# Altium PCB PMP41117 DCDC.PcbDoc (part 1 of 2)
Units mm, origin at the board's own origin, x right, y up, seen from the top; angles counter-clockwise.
Board outline 26.81 x 27.2 mm, 4 copper layers (Top Layer, Signal Layer 1, Signal Layer 2, Bottom Layer), stack 1.016 mm thick; 79 components, 59 nets, 285 pads, 212 vias.
Unrouted connection lines stored in the file: 2.
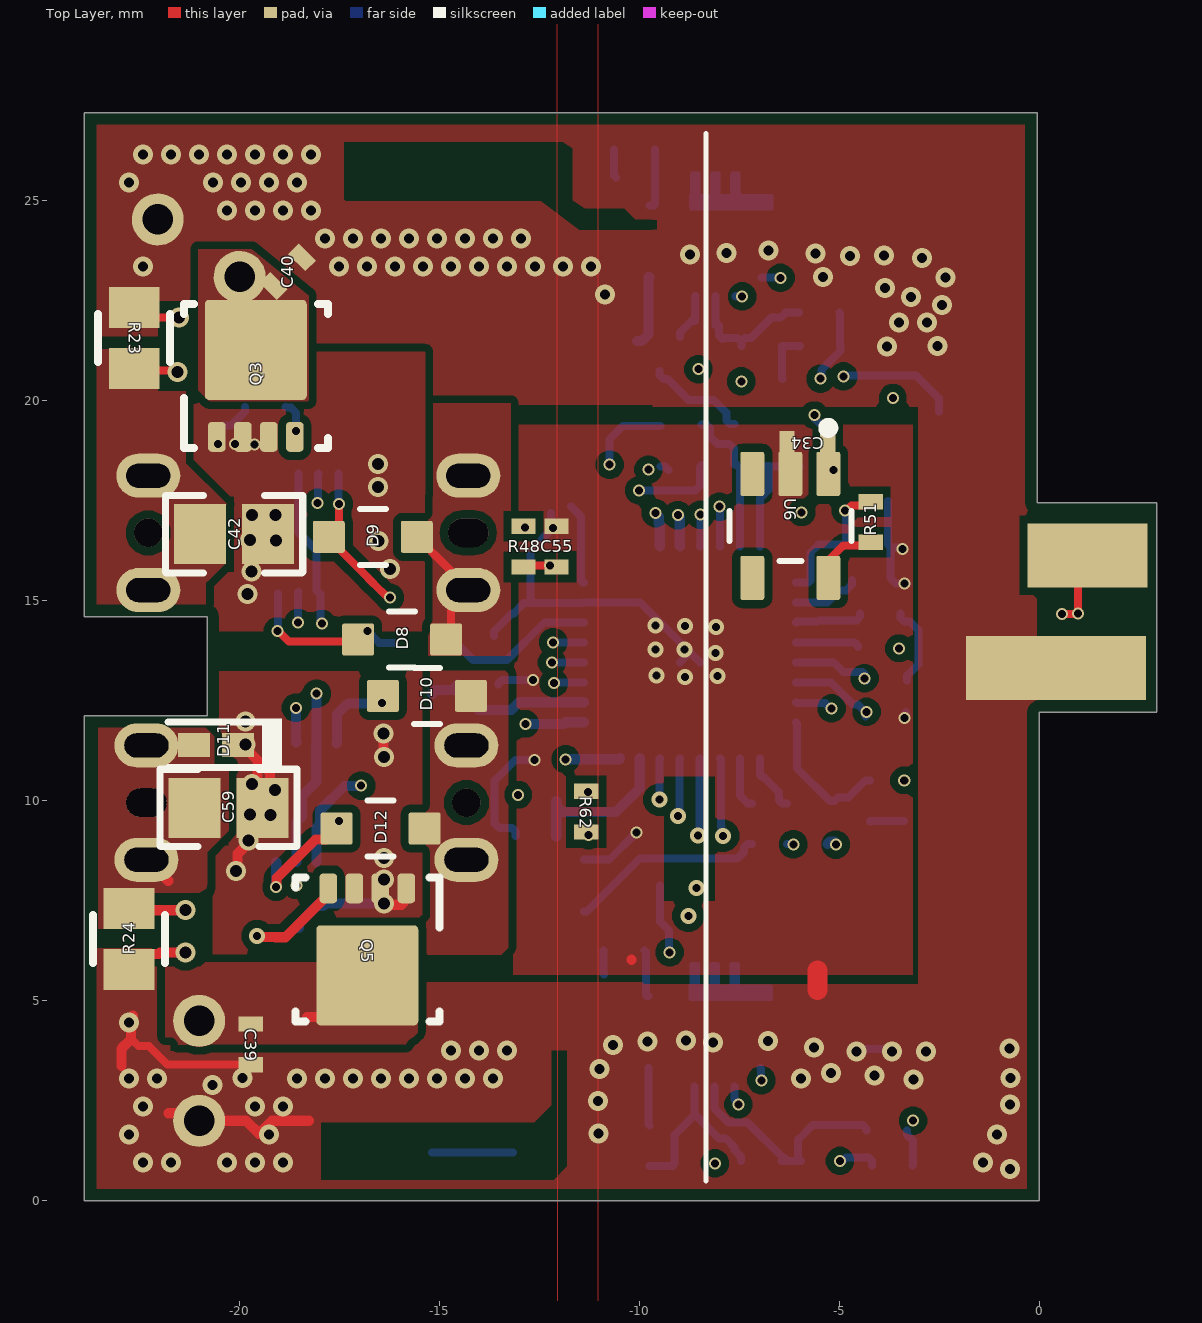
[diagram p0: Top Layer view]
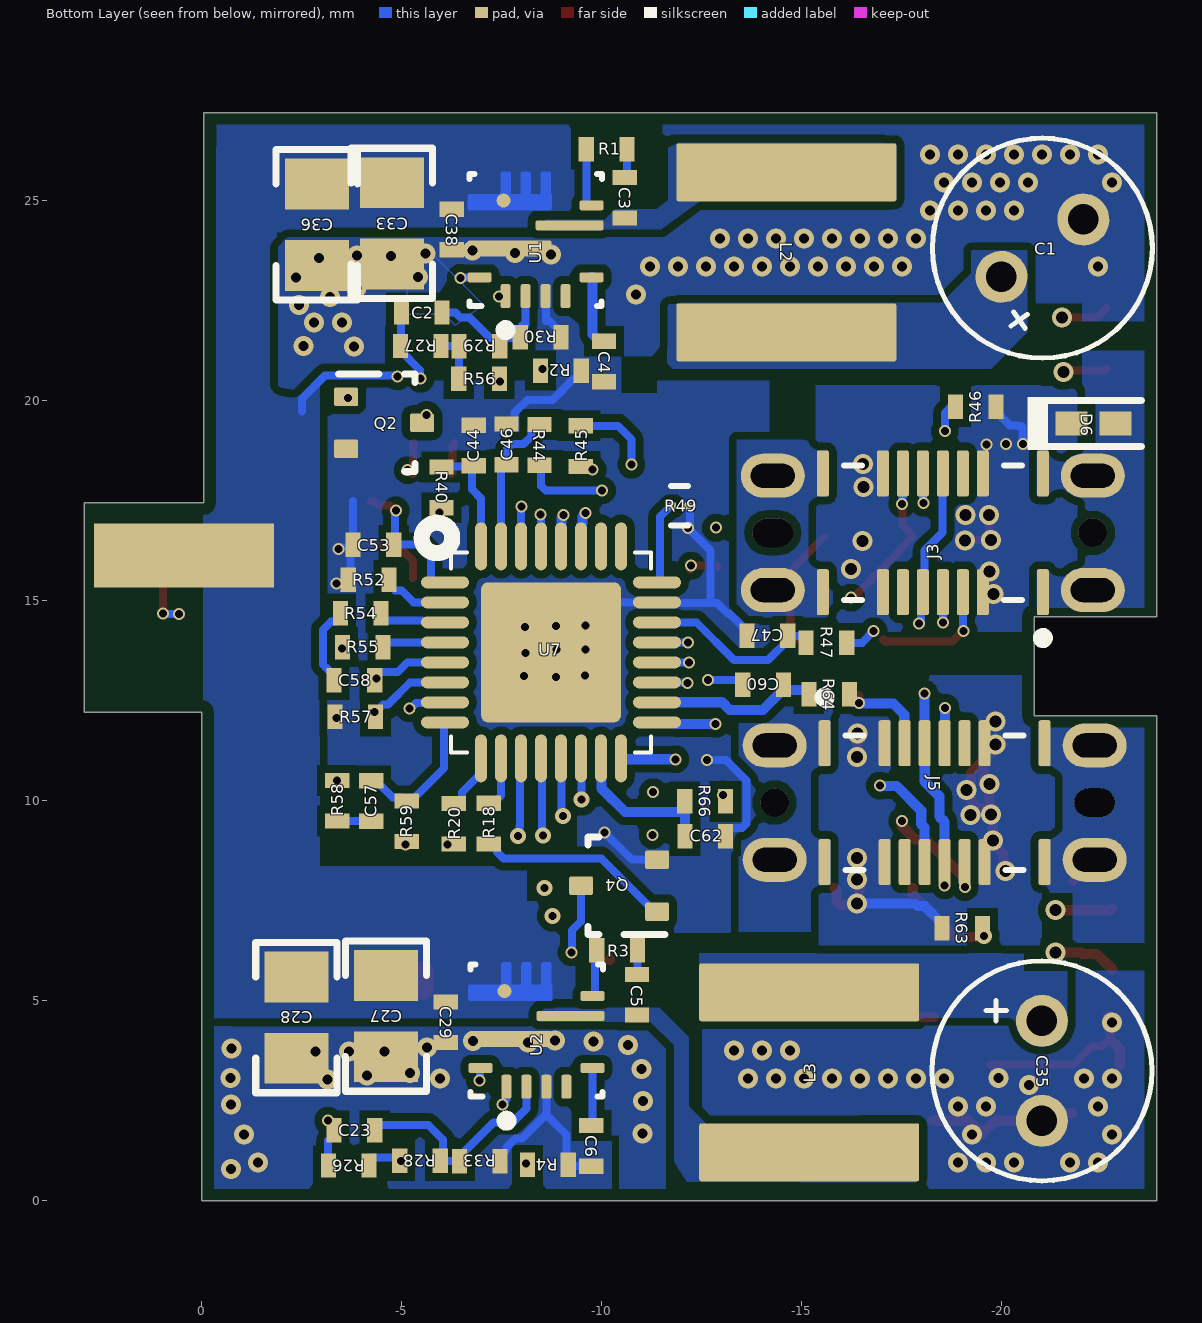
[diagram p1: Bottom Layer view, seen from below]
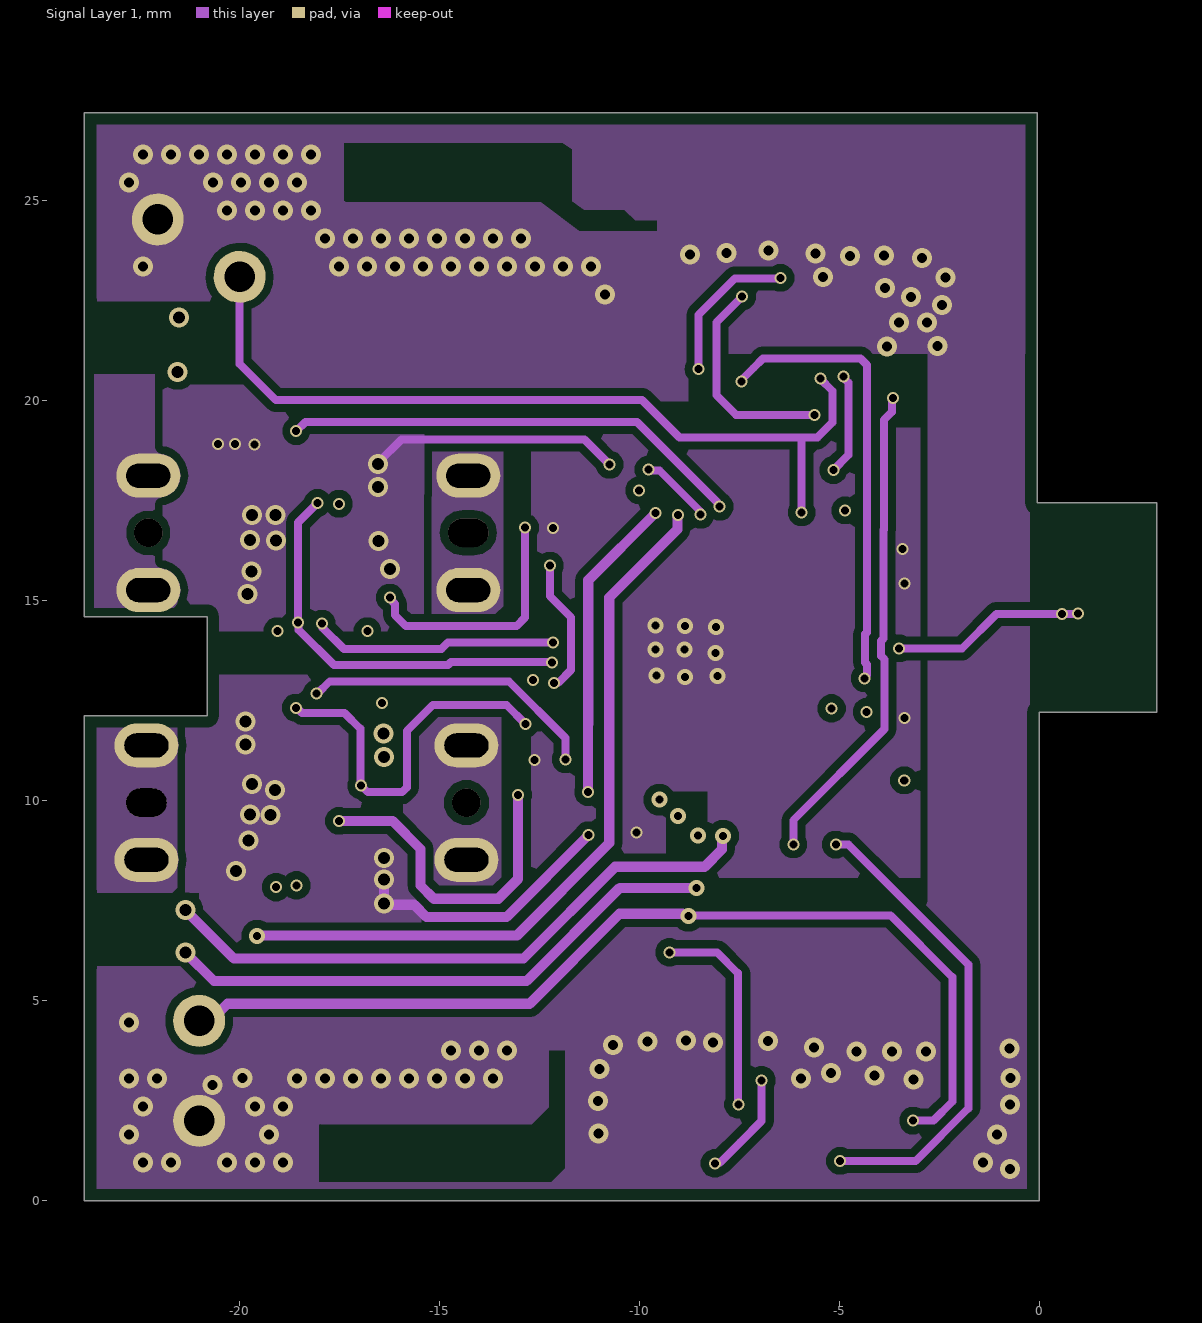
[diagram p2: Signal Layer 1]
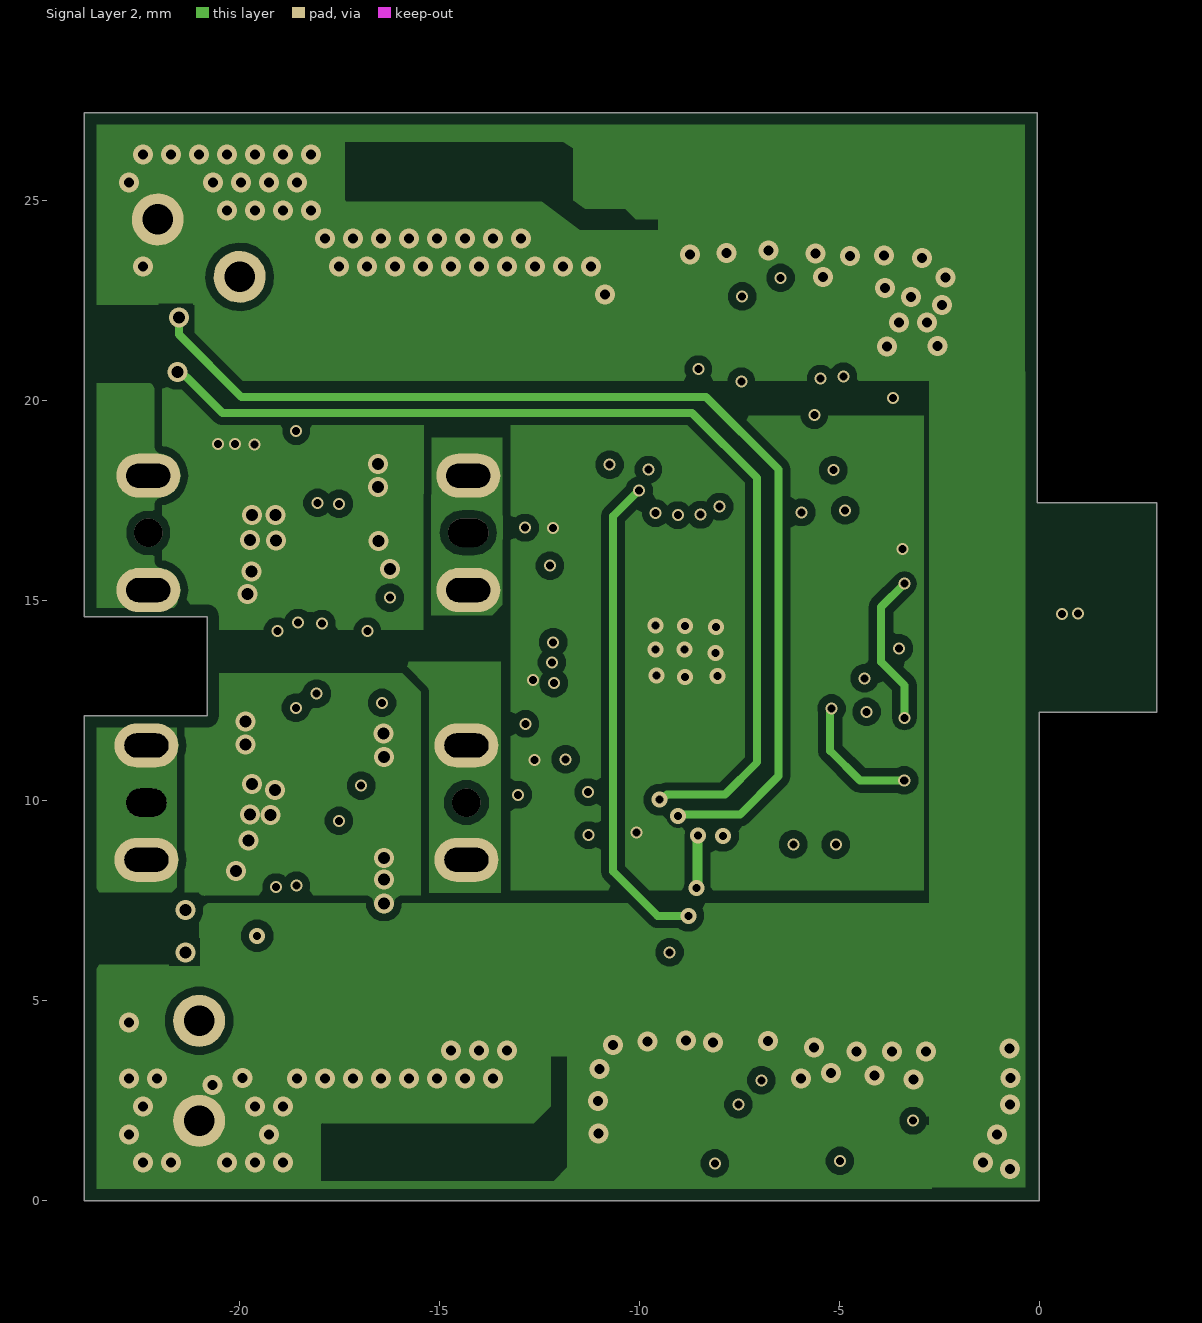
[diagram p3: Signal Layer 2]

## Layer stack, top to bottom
Top Solder: solder mask 0.0102, Solder Resist, Dk 3.5
Top Layer: signal copper 0.0711
Dielectric 1: prepreg 0.127, FR-4 High Tg, Dk 4.2
Signal Layer 1: signal copper 0.0356
Dielectric 2: core 0.5486, FR-4 High Tg, Dk 4.2
Signal Layer 2: signal copper 0.0356
Dielectric 3: prepreg 0.127, FR-4 High Tg, Dk 4.2
Bottom Layer: signal copper 0.0711
Bottom Solder: solder mask 0.0102, Solder Resist, Dk 3.5

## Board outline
-23.866,-0.008 -23.866,12.127 -20.803,12.127 -20.803,14.601 -23.87,14.601 -23.87,27.192 -23.866,27.196 -0.051,27.196 -0.051,17.446 2.94,17.446 2.94,12.211 0.002,12.211 0.002,-0.008

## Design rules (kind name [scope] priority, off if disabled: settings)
AcuteAngle [All] p1: minimum=4.50000000000000E+0001 checktracksonly=FALSE
AssemblyTestPointUsage [All] p1: valid=2
BoardOutlineClearance BoardOutlineClearance_MountingHoles [OnCopper and InComponentClass('Mounting Holes')] p1: gap=0.3 ignorepadtopadclearanceinfootprint=FALSE
BoardOutlineClearance BoardOutlineClearance_Poly [OnCopper and IsPoly] p2: gap=0.3 ignorepadtopadclearanceinfootprint=FALSE
BoardOutlineClearance [OnCopper and Not InComponentClass('Logo') and not InComponentClass('FiducialMark') and not InRegion(1000,500,4000,800) and not InPoly] p3: gap=0.3 ignorepadtopadclearanceinfootprint=FALSE
Clearance Clearance_VAC_PGND [InNetClass('VAC') vs InNetClass('PGND')] p1: gap=2.286 ignorepadtopadclearanceinfootprint=TRUE
Clearance Clearance_HV_PGND [InNetClass('High Voltage') vs InNetClass('PGND')] p2: gap=1.016 ignorepadtopadclearanceinfootprint=TRUE
Clearance Clearance_SW_PGND [InNetClass('Switch Node') vs InNetClass('PGND')] p3: gap=0.864 ignorepadtopadclearanceinfootprint=TRUE
Clearance Clearance_AC_AC [InNetClass('VAC') vs InNetClass('VAC')] p4: gap=1.524 ignorepadtopadclearanceinfootprint=TRUE
Clearance Clearance_PGND_SGND [InNetClass('PGND') vs InNetClass('SGND')] p5: gap=4.064 ignorepadtopadclearanceinfootprint=TRUE
Clearance Clearance_HV_LV [InNetClass('High Voltage') vs InNetClass('Low Voltage')] p6: gap=0.864 ignorepadtopadclearanceinfootprint=TRUE
Clearance Clearance_SW_LV_1 [InNetClass('Switch Node') vs InNetClass('Low Voltage')] p7: gap=0.864 ignorepadtopadclearanceinfootprint=TRUE
Clearance Clearance_SW_HV [InNetClass('Switch Node') vs InNetClass('High Voltage')] p8: gap=0.864 ignorepadtopadclearanceinfootprint=TRUE
Clearance Clearance_1 [All] p9: gap=0.2 ignorepadtopadclearanceinfootprint=TRUE
Clearance Clearance_Keepouts [((IsTrack Or IsArc) And Not InPoly) And IsFree and IsKeepOut vs ((IsTrack Or IsArc) And Not InPoly) And IsFree and IsKeepOut] p10: gap=0 ignorepadtopadclearanceinfootprint=FALSE
Clearance Clearance_Poly [InPolygon] p11: gap=0.254 ignorepadtopadclearanceinfootprint=TRUE
Clearance Clearance_FiducialMark [IsKeepOut and InComponentClass('FiducialMark') vs IsPad and InComponentClass('FiducialMark')] p12: gap=0 ignorepadtopadclearanceinfootprint=FALSE
ComponentClearance ComponentClearance_MountingHoles_FiducialMarks [InComponentClass('Mounting Holes') vs InComponentClass('FiducialMark')] p1: gap=0.2 collisioncheckmode=3 verticalgap=0.2 showdistances=FALSE
ComponentClearance ComponentClearance_Shunt [InComponentClass('Header') vs InComponentClass('Shunt')] p2: gap=0 collisioncheckmode=3 verticalgap=0 showdistances=FALSE
ComponentClearance ComponentClearance_Logo [InComponentClass('Logo')] p3: gap=0.2 collisioncheckmode=3 verticalgap=0.2 showdistances=FALSE
ComponentClearance ComponentClearance_ScrewToNut [(HasFootprint('NY PMS 440 0025 PH')) vs (HasFootprint('Keystone_1902C'))] p4: gap=0.127 collisioncheckmode=3 verticalgap=0.254 showdistances=FALSE
ComponentClearance ComponentClearance_MountingHoles [InComponentClass('Mounting Holes')] p5: gap=1 collisioncheckmode=3 verticalgap=2540 showdistances=FALSE
ComponentClearance ComponentClearance_SmallPassives [HasFootprint('0201*') or HasFootprint('0402*') or HasFootprint('0508') or HasFootprint('0603*') or HasFootprint('0612') or HasFootprint('0805*') or HasFootprint('0815*') or HasFootprint('0830*') or HasFootprint('1206*') or HasFootprint('1210*') or HasFootprint('1808*') or HasFootprint('1812*') or HasFootprint('1825*') or HasFootprint('2010*') or HasFootprint('2220*') or HasFootprint('2225*') or HasFootprint('2512*') or HasFootprint('2728*') or HasFootprint('3518*') vs HasFootprint('0201*') or HasFootprint('0402*') or HasFootprint('0508') or HasFootprint('0603*') or HasFootprint('0612') or HasFootprint('0805*') or HasFootprint('0815*') or HasFootprint('0830*') or HasFootprint('1206*') or HasFootprint('1210*') or HasFootprint('1808*') or HasFootprint('1812*') or HasFootprint('1825*') or HasFootprint('2010*') or HasFootprint('2220*') or HasFootprint('2225*') or HasFootprint('2512*') or HasFootprint('2728*') or HasFootprint('3518*')] p6: gap=0.2 collisioncheckmode=3 verticalgap=0.2 showdistances=FALSE
ComponentClearance ComponentClearance_THtoSMT [IsThruComponent vs IsSMTComponent] p7: gap=0.2 collisioncheckmode=3 verticalgap=0.2 showdistances=FALSE
ComponentClearance ComponentClearance_THtoTH [IsThruComponent vs IsThruComponent] p8: gap=0.2 collisioncheckmode=3 verticalgap=0.2 showdistances=FALSE
ComponentClearance [All] p9: gap=0.1 collisioncheckmode=3 verticalgap=0.1 showdistances=FALSE
DiffPairsRouting DiffPair_DiffPairsRouting [All] p1: maxlimit=0.254 minlimit=0.254 mostfreqgap=0.254 toplayer_minwidth=0.254 toplayer_maxwidth=0.254 toplayer_prefwidth=0.254 midlayer1_minwidth=0.254 midlayer1_maxwidth=0.254 midlayer1_prefwidth=0.254 midlayer2_minwidth=0.254 midlayer2_maxwidth=0.254 midlayer2_prefwidth=0.254 bottomlayer_minwidth=0.254 bottomlayer_maxwidth=0.254 bottomlayer_prefwidth=0.254 filterlayerstackid={9F2BDCAB-BF4A-4FAE-9F57-695CEC5DA6CF} maxuncoupledlength=12.7
DiffPairsRouting DiffPair_DiffPairsRouting_1 [InDifferentialPair ('NewDifferentialPair1')] p2: maxlimit=0.203 minlimit=0.203 mostfreqgap=0.203 toplayer_minwidth=0.254 toplayer_maxwidth=0.254 toplayer_prefwidth=0.254 midlayer1_minwidth=0.254 midlayer1_maxwidth=0.254 midlayer1_prefwidth=0.254 midlayer2_minwidth=0.254 midlayer2_maxwidth=0.254 midlayer2_prefwidth=0.254 bottomlayer_minwidth=0.254 bottomlayer_maxwidth=0.254 bottomlayer_prefwidth=0.254 filterlayerstackid={9F2BDCAB-BF4A-4FAE-9F57-695CEC5DA6CF} maxuncoupledlength=12.7
DiffPairsRouting DiffPair_DiffPairsRouting_2 [InDifferentialPair ('NewDifferentialPair1')] p3: maxlimit=0.127 minlimit=0.127 mostfreqgap=0.127 toplayer_minwidth=0.254 toplayer_maxwidth=0.254 toplayer_prefwidth=0.254 midlayer1_minwidth=0.254 midlayer1_maxwidth=0.254 midlayer1_prefwidth=0.254 midlayer2_minwidth=0.254 midlayer2_maxwidth=0.254 midlayer2_prefwidth=0.254 bottomlayer_minwidth=0.254 bottomlayer_maxwidth=0.254 bottomlayer_prefwidth=0.254 filterlayerstackid={9F2BDCAB-BF4A-4FAE-9F57-695CEC5DA6CF} maxuncoupledlength=12.7
DiffPairsRouting DiffPair_DiffPairsRouting_3 [InDifferentialPair ('NewDifferentialPair1')] p4: maxlimit=0.178 minlimit=0.178 mostfreqgap=0.178 toplayer_minwidth=0.254 toplayer_maxwidth=0.254 toplayer_prefwidth=0.254 midlayer1_minwidth=0.254 midlayer1_maxwidth=0.254 midlayer1_prefwidth=0.254 midlayer2_minwidth=0.254 midlayer2_maxwidth=0.254 midlayer2_prefwidth=0.254 bottomlayer_minwidth=0.254 bottomlayer_maxwidth=0.254 bottomlayer_prefwidth=0.254 filterlayerstackid={9F2BDCAB-BF4A-4FAE-9F57-695CEC5DA6CF} maxuncoupledlength=12.7
DiffPairsRouting DiffPair_DiffPairsRouting_4 [InDifferentialPair ('NewDifferentialPair1')] p5: maxlimit=0.254 minlimit=0.254 mostfreqgap=0.254 toplayer_minwidth=0.381 toplayer_maxwidth=0.381 toplayer_prefwidth=0.381 midlayer1_minwidth=0.381 midlayer1_maxwidth=0.381 midlayer1_prefwidth=0.381 midlayer2_minwidth=0.381 midlayer2_maxwidth=0.381 midlayer2_prefwidth=0.381 bottomlayer_minwidth=0.381 bottomlayer_maxwidth=0.381 bottomlayer_prefwidth=0.381 filterlayerstackid={9F2BDCAB-BF4A-4FAE-9F57-695CEC5DA6CF} maxuncoupledlength=12.7
DiffPairsRouting DiffPair_DiffPairsRouting_5 [All] p6: maxlimit=0.254 minlimit=0.254 mostfreqgap=0.254 toplayer_minwidth=0.254 toplayer_maxwidth=0.254 toplayer_prefwidth=0.254 midlayer1_minwidth=0.254 midlayer1_maxwidth=0.254 midlayer1_prefwidth=0.254 midlayer2_minwidth=0.254 midlayer2_maxwidth=0.254 midlayer2_prefwidth=0.254 bottomlayer_minwidth=0.254 bottomlayer_maxwidth=0.254 bottomlayer_prefwidth=0.254 filterlayerstackid={9F2BDCAB-BF4A-4FAE-9F57-695CEC5DA6CF} maxuncoupledlength=12.7
DiffPairsRouting DiffPair_DiffPairsRouting_6 [All] p7: maxlimit=0.254 minlimit=0.254 mostfreqgap=0.254 toplayer_minwidth=0.254 toplayer_maxwidth=0.254 toplayer_prefwidth=0.254 midlayer1_minwidth=0.254 midlayer1_maxwidth=0.254 midlayer1_prefwidth=0.254 midlayer2_minwidth=0.254 midlayer2_maxwidth=0.254 midlayer2_prefwidth=0.254 bottomlayer_minwidth=0.254 bottomlayer_maxwidth=0.254 bottomlayer_prefwidth=0.254 filterlayerstackid={9F2BDCAB-BF4A-4FAE-9F57-695CEC5DA6CF} maxuncoupledlength=12.7
DiffPairsRouting DiffPair_DiffPairsRouting_7 [InDifferentialPair ('NewDifferentialPair2')] p8: maxlimit=0.254 minlimit=0.254 mostfreqgap=0.254 toplayer_minwidth=0.254 toplayer_maxwidth=0.254 toplayer_prefwidth=0.254 midlayer1_minwidth=0.254 midlayer1_maxwidth=0.254 midlayer1_prefwidth=0.254 midlayer2_minwidth=0.254 midlayer2_maxwidth=0.254 midlayer2_prefwidth=0.254 bottomlayer_minwidth=0.254 bottomlayer_maxwidth=0.254 bottomlayer_prefwidth=0.254 filterlayerstackid={9F2BDCAB-BF4A-4FAE-9F57-695CEC5DA6CF} maxuncoupledlength=12.7
DiffPairsRouting DiffPair_DiffPairsRouting_8 [InDifferentialPair ('NewDifferentialPair2')] p9: maxlimit=0.254 minlimit=0.254 mostfreqgap=0.254 toplayer_minwidth=0.381 toplayer_maxwidth=0.381 toplayer_prefwidth=0.381 midlayer1_minwidth=0.381 midlayer1_maxwidth=0.381 midlayer1_prefwidth=0.381 midlayer2_minwidth=0.381 midlayer2_maxwidth=0.381 midlayer2_prefwidth=0.381 bottomlayer_minwidth=0.381 bottomlayer_maxwidth=0.381 bottomlayer_prefwidth=0.381 filterlayerstackid={9F2BDCAB-BF4A-4FAE-9F57-695CEC5DA6CF} maxuncoupledlength=12.7
DiffPairsRouting DiffPair_DiffPairsRouting_9 [InDifferentialPair ('ISense_A')] p10: maxlimit=0.198 minlimit=0.198 mostfreqgap=0.198 toplayer_minwidth=0.254 toplayer_maxwidth=0.254 toplayer_prefwidth=0.254 midlayer1_minwidth=0.254 midlayer1_maxwidth=0.254 midlayer1_prefwidth=0.254 midlayer2_minwidth=0.254 midlayer2_maxwidth=0.254 midlayer2_prefwidth=0.254 bottomlayer_minwidth=0.254 bottomlayer_maxwidth=0.254 bottomlayer_prefwidth=0.254 filterlayerstackid={9F2BDCAB-BF4A-4FAE-9F57-695CEC5DA6CF} maxuncoupledlength=12.7
DiffPairsRouting DiffPair_DiffPairsRouting_10 [InDifferentialPair ('ISense_A')] p11: maxlimit=0.254 minlimit=0.254 mostfreqgap=0.254 toplayer_minwidth=0.381 toplayer_maxwidth=0.381 toplayer_prefwidth=0.381 midlayer1_minwidth=0.381 midlayer1_maxwidth=0.381 midlayer1_prefwidth=0.381 midlayer2_minwidth=0.381 midlayer2_maxwidth=0.381 midlayer2_prefwidth=0.381 bottomlayer_minwidth=0.381 bottomlayer_maxwidth=0.381 bottomlayer_prefwidth=0.381 filterlayerstackid={9F2BDCAB-BF4A-4FAE-9F57-695CEC5DA6CF} maxuncoupledlength=12.7
DiffPairsRouting DiffPair_DiffPairsRouting_11 [InDifferentialPair ('ISense_A')] p12: maxlimit=0.254 minlimit=0.254 mostfreqgap=0.254 toplayer_minwidth=0.381 toplayer_maxwidth=0.381 toplayer_prefwidth=0.381 midlayer1_minwidth=0.381 midlayer1_maxwidth=0.381 midlayer1_prefwidth=0.381 midlayer2_minwidth=0.381 midlayer2_maxwidth=0.381 midlayer2_prefwidth=0.381 bottomlayer_minwidth=0.381 bottomlayer_maxwidth=0.381 bottomlayer_prefwidth=0.381 filterlayerstackid={9F2BDCAB-BF4A-4FAE-9F57-695CEC5DA6CF} maxuncoupledlength=12.7
DiffPairsRouting DiffPair_ADiffPairsRouting [All] p13: maxlimit=0.198 minlimit=0.198 mostfreqgap=0.198 toplayer_minwidth=0.254 toplayer_maxwidth=0.254 toplayer_prefwidth=0.254 midlayer1_minwidth=0.254 midlayer1_maxwidth=0.254 midlayer1_prefwidth=0.254 midlayer2_minwidth=0.254 midlayer2_maxwidth=0.254 midlayer2_prefwidth=0.254 bottomlayer_minwidth=0.254 bottomlayer_maxwidth=0.254 bottomlayer_prefwidth=0.254 filterlayerstackid={9F2BDCAB-BF4A-4FAE-9F57-695CEC5DA6CF} maxuncoupledlength=12.7
DiffPairsRouting [All] p14: maxlimit=2.54 minlimit=0.254 mostfreqgap=0.254 toplayer_minwidth=0.381 toplayer_maxwidth=0.381 toplayer_prefwidth=0.381 midlayer1_minwidth=0.381 midlayer1_maxwidth=0.381 midlayer1_prefwidth=0.381 midlayer2_minwidth=0.381 midlayer2_maxwidth=0.381 midlayer2_prefwidth=0.381 bottomlayer_minwidth=0.381 bottomlayer_maxwidth=0.381 bottomlayer_prefwidth=0.381 maxuncoupledlength=25.4
FabricationTestPointUsage TestPointUsage [All] p1: valid=2 allowmultiple=FALSE
FabricationTestpoint Testpoint [All] p1: side=3 testpointundercomponent=TRUE minsize=1.016 maxsize=2.54 preferedsize=1.524 minholesize=0 maxholesize=1.016 preferedholesize=0.813 testpointgrid=0.025 allowsidetop=TRUE allowsidebottom=TRUE usegrid=TRUE gridtolerance=0
FanoutControl Fanout_LCC [IsLCC] p1: bgadir=Out bgaviamode=Centered fanoutstyle=Auto fanoutdirection=Alternating viagrid=0.025 // Fanout_LCC (Default Rule)
FanoutControl Fanout_BGA [IsBGA] p2: bgadir=Out bgaviamode=Centered fanoutstyle=Auto fanoutdirection=Alternating viagrid=0.025 // Fanout_BGA (Default Rule)
HoleSize [All] p1: absolutevalues=TRUE maxlimit=6.375 minlimit=0.2 maxpercent=80.000 minpercent=20.000
MatchedLengths DiffPair_MatchedLengths [All] p1: tolerance=25.4 checknetsindiffpair=FALSE checkdiffpairvsdiffpair=TRUE checkxsignals=TRUE checkothers=TRUE
MatchedLengths DiffPair_MatchedLengths_1 [InDifferentialPair ('NewDifferentialPair1')] p2: tolerance=25.4 checknetsindiffpair=FALSE checkdiffpairvsdiffpair=TRUE checkxsignals=TRUE checkothers=TRUE
MatchedLengths DiffPair_MatchedLengths_2 [InDifferentialPair ('NewDifferentialPair1')] p3: tolerance=25.4 checknetsindiffpair=FALSE checkdiffpairvsdiffpair=TRUE checkxsignals=TRUE checkothers=TRUE
MatchedLengths DiffPair_MatchedLengths_3 [InDifferentialPair ('NewDifferentialPair1')] p4: tolerance=25.4 checknetsindiffpair=FALSE checkdiffpairvsdiffpair=TRUE checkxsignals=TRUE checkothers=TRUE
MatchedLengths DiffPair_MatchedLengths_4 [InDifferentialPair ('NewDifferentialPair1')] p5: tolerance=25.4 checknetsindiffpair=FALSE checkdiffpairvsdiffpair=TRUE checkxsignals=TRUE checkothers=TRUE
MatchedLengths DiffPair_MatchedLengths_5 [All] p6: tolerance=25.4 checknetsindiffpair=FALSE checkdiffpairvsdiffpair=TRUE checkxsignals=TRUE checkothers=TRUE
MatchedLengths DiffPair_MatchedLengths_6 [All] p7: tolerance=25.4 checknetsindiffpair=FALSE checkdiffpairvsdiffpair=TRUE checkxsignals=TRUE checkothers=TRUE
MatchedLengths DiffPair_MatchedLengths_7 [InDifferentialPair ('NewDifferentialPair2')] p8: tolerance=25.4 checknetsindiffpair=FALSE checkdiffpairvsdiffpair=TRUE checkxsignals=TRUE checkothers=TRUE
MatchedLengths DiffPair_MatchedLengths_8 [InDifferentialPair ('NewDifferentialPair2')] p9: tolerance=25.4 checknetsindiffpair=FALSE checkdiffpairvsdiffpair=TRUE checkxsignals=TRUE checkothers=TRUE
MatchedLengths DiffPair_MatchedLengths_9 [InDifferentialPair ('ISense_A')] p10: tolerance=25.4 checknetsindiffpair=FALSE checkdiffpairvsdiffpair=TRUE checkxsignals=TRUE checkothers=TRUE
MatchedLengths DiffPair_MatchedLengths_10 [InDifferentialPair ('ISense_A')] p11: tolerance=25.4 checknetsindiffpair=FALSE checkdiffpairvsdiffpair=TRUE checkxsignals=TRUE checkothers=TRUE
MatchedLengths DiffPair_MatchedLengths_11 [InDifferentialPair ('ISense_A')] p12: tolerance=25.4 checknetsindiffpair=FALSE checkdiffpairvsdiffpair=TRUE checkxsignals=TRUE checkothers=TRUE
MatchedLengths DiffPair_AMatchedLengths [All] p13: tolerance=25.4 checknetsindiffpair=FALSE checkdiffpairvsdiffpair=TRUE checkxsignals=TRUE checkothers=TRUE
MinimumAnnularRing MinimumAnnularRing_ThermalPadVias [IsVia and InAnyComponent] p1: minimumring=0.15
MinimumAnnularRing [All] p2: minimumring=0.2
MinimumSolderMaskSliver MinimumSolderMaskSliver_Logo [InComponentClass('Logo') vs InComponentClass('Logo')] p1: minsoldermaskwidth=0.018
MinimumSolderMaskSliver [All] p2: minsoldermaskwidth=0.1
PlaneConnect [All] p1: planeconnectstyle=Relief reliefexpansion=0.254 reliefentries=4 reliefconductorwidth=0.254 reliefairgap=0.254
PolygonConnect [All] p1: connectstyle=Direct reliefconductorwidth=0.254 reliefentries=4 polygonreliefangle="90 Angle" airgapwidth=0
RoutingVias ThermalPadVias [IsVia and InAnyComponent] p1: holewidth=0.2 width=0.5 viastyle="Through Hole" minholewidth=0.2 minwidth=0.5 maxholewidth=0.33 maxwidth=0.6
RoutingVias [All] p2: holewidth=0.406 width=0.864 viastyle="Through Hole" minholewidth=0.2 minwidth=0.61 maxholewidth=1.016 maxwidth=1.651
SilkToSilkClearance SilkToSilkClearance_Pb-FreeLogo [(HasFootprint('Pb-Free_Overlay_Medium') OR HasFootprint('Pb-Free_Overlay_Small')) vs (HasFootprint('Pb-Free_Overlay_Medium') OR HasFootprint('Pb-Free_Overlay_Small'))] p1: silktosilkclearance=0
SilkToSilkClearance [All] p2: silktosilkclearance=0.1
SilkToSolderMaskClearance SilkToComponentPadClearance [(IsPad or IsFill or IsRegion) and InAnycomponent] p1: minsilkscreentomaskgap=0.127 clearancetoexposedcopper=TRUE
SilkToSolderMaskClearance "Silk to Solder Mask Opening" [All] p2: minsilkscreentomaskgap=0.1 clearancetoexposedcopper=FALSE
SolderMaskExpansion [All] p1: expansion=0.05 istentingtop=FALSE
UnRoutedNet [All] p1: checkbadconnections=TRUE
Width [All] p1: maxlimit=2.54 minlimit=0.152 preferedwidth=0.2 checkconnectedcopper=TRUE
17 further rules are at their usual default settings.

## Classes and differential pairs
component class "Dual Port DCDC": C1 C2 C3 C4 C5 C6 C23 C27 C28 C29 C33 C35 C36 C38 C39 C40 L2 L3 Q2 Q4 R1 R2 R3 R4 R26 R27 R28 R29 R30 R33 U1 U2
component class "2C PD Controller": C34 C42 C44 C46 C47 C53 C55 C57 C58 C59 C60 C62 D6 D8 D9 D10 D11 D12 J3 J5 Q3 Q5 R18 R20 R23 R24 R40 R44 R45 R46 R47 R48 R49 R51 R52 R54 R55 R56 R57 R58 R59 R62 R63 R64 R66 U6 U7

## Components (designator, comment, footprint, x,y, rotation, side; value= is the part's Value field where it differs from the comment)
C1 "CAP 25V 150uF D 5.5X7mm" Ecap_5.5_9_2.5 -19.986,23.094 r145 bottom value=150uF
C2 "CGA2B2C0G1H151J050BA" 0402S -5.496,22.203 r180 bottom value=150pF
C3 "0402BB104KW500" 0402S -10.573,25.072 r270 bottom value=0.1uF
C4 "C1005X5R1H473K050BB" 0402S -10.052,20.979 r270 bottom value=0.047uF
C5 "0402BB104KW500" 0402S -10.876,5.146 r270 bottom value=0.1uF
C6 "C1005X5R1H473K050BB" 0402S -9.736,1.369 r270 bottom value=0.047uF
C23 "CGA2B2C0G1H151J050BA" 0402S -3.809,1.757 r180 bottom value=150pF
C27 "GMK212BBJ106KG-T" 0805_HV -4.601,4.614 r270 bottom value=10uF
C28 "GMK212BBJ106KG-T" 0805_HV -2.361,4.575 r270 bottom value=10uF
C29 "GMK105BJ104KV-F" 0402S -6.097,4.458 r270 bottom value=0.1uF
C33 "GMK212BBJ106KG-T" 0805_HV -4.748,24.429 r270 bottom value=10uF
C34 "GRM155R61E225KE11D" 0402_070 -5.795,18.94 r180 top value=2.2uF
C35 "CAP 25V 150uF D 5.5X7mm" Ecap_5.5_9_2.5 -21,4.495 r270 bottom value=150uF
C36 "GMK212BBJ106KG-T" 0805_HV -2.87,24.396 r270 bottom value=10uF
C38 "GMK105BJ104KV-F" 0402S -6.244,24.277 r270 bottom value=0.1uF
C39 "GMK105BJ104KV-F" 0402S -19.711,3.906 r270 top value=0.1uF
C40 "GMK105BJ104KV-F" 0402S -18.785,23.223 r45 top value=0.1uF
C42 "GMK212BBJ106KG-T" 0805 -20.127,16.661 r180 top value=10uF
C44 "GRM155R61E105KA12D" 0402S -6.797,18.877 r90 bottom value=1uF
C46 "GRM155R61E105KA12D" 0402S -7.615,18.906 r90 bottom value=1uF
C47 "GRM155R71H221KA01D" 0402S -14.137,14.117 r0 bottom value=220pF
C53 "GRM155R61E225KE11D" 0402_070 -4.287,16.397 r180 bottom value=2.2uF
C55 "GRM155R71H221KA01D" 0402S -12.065,16.348 r90 top value=220pF
C57 "CGA2B2X7R1H332K050BA" 0402S -4.231,9.991 r90 bottom value=3300pF
C58 "CGA2B2X7R1H332K050BA" 0402S -3.812,13.009 r180 bottom value=3300pF
C59 "GMK212BBJ106KG-T" 0805 -20.266,9.817 r180 top value=10uF
C60 "GRM155R71H221KA01D" 0402S -14.029,12.898 r0 bottom value=220pF
C62 "GRM155R71H221KA01D" 0402S -12.582,9.11 r180 bottom value=220pF
D6 "RB521SM-40T2R" SOD-523 -22.293,19.428 r180 bottom value=40V
D8 "STS321050B331" FP-STS321050B331_SOD-323-MFG -15.925,14.026 r180 top
D9 "STS321050B331" FP-STS321050B331_SOD-323-MFG -16.659,16.595 r180 top
D10 "STS321050B331" FP-STS321050B331_SOD-323-MFG -15.307,12.617 r180 top
D11 "RB521SM-40T2R" SOD-523 -20.577,11.394 r180 top value=40V
D12 "STS321050B331" FP-STS321050B331_SOD-323-MFG -16.463,9.3 r180 top
J3 "USB4145-03-0230-C" FP-USB4145-03-0230-C_CONN_USB-MFG -18.272,16.694 r0 bottom
J5 "USB4145-03-0230-C" FP-USB4145-03-0230-C_CONN_USB-MFG -18.318,9.949 r180 bottom
L2 "74439346056" WE-XHMI_6060 -14.609,23.707 r270 bottom value=5.6uH
L3 "74439346056" WE-XHMI_6060 -15.182,3.207 r90 bottom value=5.6uH
Q2 "2N7002KW" SOT-323 -4.553,19.444 r180 bottom value=60V
Q3 "CSD17575Q3" DQG0008A -19.584,20.62 r90 top value=30V
Q4 "2N7002KW" SOT-323 -10.43,7.871 r0 bottom value=60V
Q5 "CSD17575Q3" DQG0008A -16.797,6.283 r270 top value=30V
R1 "CRCW04021R00JNED" 0402S -10.116,26.28 r180 bottom value=1.0
R2 "CRCW040230K1FKED" 0402S -8.972,20.751 r0 bottom value=30.1k
R3 "CRCW04021R00JNED" 0402S -10.379,6.256 r180 bottom value=1.0
R4 "CRCW040230K1FKED" 0402S -8.648,0.892 r0 bottom value=30.1k
R18 "CRCW04021R00JNED" 0402S -7.174,9.426 r90 bottom value=1.0
R20 "CRCW04021R00JNED" 0402S -6.299,9.42 r90 bottom value=1.0
R23 "WSL08055L000FEA" WSL0805 -22.623,21.566 r270 top value=0.005
R24 "WSL08055L000FEA" WSL0805 -22.757,6.541 r90 top value=0.005
R26 "CRCW0402100KDHEDP" 0402S -3.67,0.878 r0 bottom value=100k
R27 "CRCW0402100KDHEDP" 0402S -5.47,21.364 r0 bottom value=100k
R28 "CRCW04025K62FKED" 0402S -5.45,0.994 r0 bottom value=5.62k
R29 "CRCW04025K62FKED" 0402S -6.937,21.36 r0 bottom value=5.62k
R30 "CRCW040214K3FKED" 0402S -8.468,21.588 r0 bottom value=14.3k
R33 "CRCW040214K3FKED" 0402S -6.944,0.988 r0 bottom value=14.3k
R40 "CRCW04021R00JNED" 0402S -5.989,17.83 r270 bottom value=1.0
R44 "CRCW04021R00JNED" 0402S -8.438,18.892 r270 bottom value=1.0
R45 "MCR01MZPF1001" 0402S -9.468,18.862 r90 bottom value=1.00k
R46 "RMCF0402FT1M00" 0402S -19.346,19.843 r0 bottom value=1.0Meg
R47 "CRCW040247R0JNED" 0402S -15.612,13.945 r180 bottom value=47
R48 "CRCW040247R0JNED" 0402S -12.892,16.348 r90 top value=47
R49 "NTCG043JF103FTB" FP-NTCG043JF103FTB_SMD2-MFG -11.956,17.363 r180 bottom value=10k
R51 "CRCW04021R00JNED" 0402S -4.212,16.965 r90 top value=1.0
R52 "MCR01MZPF1001" 0402S -4.168,15.519 r180 bottom value=1.00k
R54 "CRCW0402200KFKED" 0402S -3.97,14.683 r180 bottom value=200k
R55 "CRCW04021R00JNED" 0402S -4.019,13.837 r180 bottom value=1.0
R56 "MCR01MZPF1001" 0402S -6.928,20.542 r180 bottom value=1.00k
R57 "MCR01MZPF1001" 0402S -3.833,12.098 r180 bottom value=1.00k
R58 "CRCW0402200KFKED" 0402S -3.381,9.996 r90 bottom value=200k
R59 "MCR01MZPF1001" 0402S -5.117,9.484 r90 bottom value=1.00k
R62 "MCR01MZPF1001" 0402S -11.323,9.723 r270 top value=1.00k
R63 "RMCF0402FT1M00" 0402S -19.009,6.813 r180 bottom value=1.0Meg
R64 "CRCW040247R0JNED" 0402S -15.681,12.663 r180 bottom value=47
R66 "CRCW040247R0JNED" 0402S -12.58,9.982 r180 bottom value=47
U1 "TPS56837HRPAR" RPA0010A-MFG -8.341,24.012 r90 bottom
U2 "TPS56837HRPAR" RPA0010A-MFG -8.363,4.247 r90 bottom
U6 "TLV709A33DBVR" DBV0005A-MFG -6.222,16.869 r270 top
U7 "IP2738" IP2738 -6.077,15.457 r180 bottom

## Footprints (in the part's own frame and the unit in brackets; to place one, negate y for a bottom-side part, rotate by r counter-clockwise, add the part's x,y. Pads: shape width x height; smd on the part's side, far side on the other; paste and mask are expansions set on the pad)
0402_070 [mil] "SMD, 2-Leads, Body 1.2x0.7mm, Height 0.7mm"
  rect 15x24 smd: 1(-20,0) 2(20,0)
  body extent -24,-14 24,14, height 28
0402S [mil] "Based on C0402S footprint from PADS legacy"
  rect 15x24 smd: 1(-20,0) 2(20,0)
  body extent -22,-12 22,12, height 24
0805 [mm] "0805 from SM-752 data"
  rect 1.3x1.5 smd: 1(-0.85,0) 2(0.85,0)
  silkscreen extent -1.72,-0.97 1.72,0.97, body extent -1.1,-0.72 1.1,0.72, height 1.45
0805_HV [mil] "0805 with 30mil clearance between pads"
  rect 50x63 smd: 1(-40,0) 2(40,0)
  silkscreen extent -74,-40 74,40, body extent -43,-29 43,29, height 57
DBV0005A-MFG [mm]
  rrect17% 1.1x0.6 smd paste+0 mask+0: 1(-1.3,0.95) 2(-1.3,0) 3(-1.3,-0.95) 4(1.3,-0.95) 5(1.3,0.95)
  silkscreen extent -2.57,-1.53 0.87,1.53, body extent -1.4,-1.45 1.4,1.45, height 1.45
DQG0008A [mm] "SMD, 8-Leads, Body 3.3x3.3mm, Pitch 0.65mm"
  rrect45% 0.75x0.44 smd paste-0.05 mask-0.05: 1(-1.525,0.975) 2(-1.525,0.325) 3(-1.525,-0.325) 4(-1.525,-0.975) 5(1.525,-0.975) 6(1.525,-0.325) 7(1.525,0.325) 8(1.525,0.975)
  rrect50% 0.676x1.125 on Top Paste: 9(-0.212,0.662) 9(-0.212,-0.663) 9(0.664,-0.663) 9(0.664,0.662)
  rrect50% 1.775x2.45 on Top Solder: 9(0.327,0)
  rrect8% 2.5x2.55 smd paste-1.5 mask-1.5: 9(0.65,0)
  rrect50% 0.5x0.34 on Top Solder: 9(1.175,-0.975) 9(1.175,-0.325) 9(1.175,0.325) 9(1.175,0.975)
  silkscreen extent -1.8,-1.8 1.8,1.8, body extent -1.65,-1.65 1.65,1.65, height 1.1
Ecap_5.5_9_2.5 [mm]
  round 1.3 hole 0.762: 1(2.5,0) 2(0,0)
  silkscreen extent -1.5,-2.75 4,2.75
FP-NTCG043JF103FTB_SMD2-MFG [mm]
  rrect56% 0.18x0.19 smd paste+0 mask+0: 1(-0.19,0) 2(0.19,0)
  silkscreen extent -0.23,-0.49 0.2,0.5, body extent -0.2,-0.1 0.2,0.1, height 0.22
FP-STS321050B331_SOD-323-MFG [mm]
  rrect13% 0.8x0.8 smd paste+0 mask+0: 1(-1.1,0) 2(1.1,0)
  silkscreen extent -0.33,-0.7 0.33,0.7, body extent -1.6,-0.8 1.6,0.8, height 0.25
FP-USB4145-03-0230-C_CONN_USB-MFG [mm]
  rrect100% 1.6x1.1 hole 0.6 slot 1.1 at 0 deg paste-1000 mask+0: 1(-4,1.43) 2(4,1.43) 3(-4,-1.43) 4(4,-1.43)
  rrect33% 0.3x1.15 smd paste+0 mask+0: A1(-2.75,1.485) A4(-1.25,1.485) A5(-0.75,1.485) A6(-0.25,1.485) A7(0.25,1.485) A8(0.75,1.485) A9(1.25,1.485) A12(2.75,1.485) B1(2.75,-1.485) B4(1.25,-1.485) B5(0.75,-1.485) B6(0.25,-1.485) B7(-0.25,-1.485) B8(-0.75,-1.485) B9(-1.25,-1.485) B12(-2.75,-1.485)
  round 0.71 hole 0.71 unplated paste-1000 mask+0: ""(-4,0)
  rrect100% 1.01x0.71 hole 0.71 slot 1.01 at 0 deg unplated paste-1000 mask+0: ""(4,0)
  silkscreen extent -2.87,-1.68 2.22,2.75, body extent -4.48,-1.85 4.47,1.84, height 7.66
IP2738 [mm]
  oval 1.2x0.3 smd: 1(0,0) 2(0,-0.5) 3(0,-1) 4(0,-1.5) 5(0,-2) 6(0,-2.5) 7(0,-3) 8(0,-3.5) 17(5.3,-3.5) 18(5.3,-3) 19(5.3,-2.5) 20(5.3,-2) 21(5.3,-1.5) 22(5.3,-1) 23(5.3,-0.5) 24(5.3,0)
  oval 0.3x1.2 smd: 9(0.9,-4.4) 10(1.4,-4.4) 11(1.9,-4.4) 12(2.4,-4.4) 13(2.9,-4.4) 14(3.4,-4.4) 15(3.9,-4.4) 16(4.4,-4.4) 25(4.4,0.9) 26(3.9,0.9) 27(3.4,0.9) 28(2.9,0.9) 29(2.4,0.9) 30(1.9,0.9) 31(1.4,0.9) 32(0.9,0.9)
  rrect10% 3.5x3.5 smd: 33(2.65,-1.75)
  silkscreen extent -0.58,-4.25 5.15,1.49
RPA0010A-MFG [mm]
  rrect40% 0.6x0.25 smd paste+0 mask+0: 1(-1.4,0.75) 2(-1.4,0.25) 3(-1.4,-0.25) 4(-1.4,-0.75)
  rrect40% 0.25x0.6 smd paste+0 mask+0: 5(-0.93,-1.4) 7(0.87,-1.4) 10(-0.93,1.4)
  rrect40% 0.25x1.7 smd paste-1000 mask+0: 6(0.37,-0.85)
  round 0.35 smd paste+0 mask+0: 8(0.99,0.8)
  rrect25% 0.4x2.1 smd paste-1000 mask+0: 9(-0.21,0.65)
  Top Layer region: 0.8,1.7 0.781,1.696 0.765,1.685 0.754,1.669 0.75,1.65 0.75,1.65 0.75,-0.35 0.754,-0.369 0.765,-0.385 0.781,-0.396 0.8,-0.4 0.8,-0.4 1.15,-0.4 1.15,-0.375 1.66,-0.375 1.685,-0.368 1.703,-0.35 1.71,-0.325 1.71,-0.325 1.71,-0.175 1.706,-0.156 1.695,-0.14 1.679,-0.129 1.66,-0.125 1.66,-0.125 1.15,-0.125 1.15,0.125 1.66,0.125 1.679,0.129 1.695,0.14 1.706,0.156 1.71,0.175 1.71,0.175 1.71,0.325 1.703,0.35 1.685,0.368 1.66,0.375 1.66,0.375 1.15,0.375 1.15,0.625 1.66,0.625 1.679,0.629 1.695,0.64 1.706,0.656 1.71,0.675 1.71,0.675 1.71,0.825 1.703,0.85 1.685,0.868 1.66,0.875 1.66,0.875 1.2,0.875 1.181,0.879 1.165,0.89 1.154,0.906 1.15,0.925 1.15,0.925 1.15,1.65 1.143,1.675 1.125,1.693 1.1,1.7 1.1,1.7
  silkscreen extent -2.37,-1.66 1.65,1.65, body extent -1.5,-1.5 1.5,1.5, height 1
SOD-523 [mm] "NXP Semiconductor recommended land pattern, nominal STEP model"
  rect 0.8x0.6 smd paste-0.05: 1(-0.55,0) 2(0.55,0)
  silkscreen extent -1.65,-0.66 1.2,0.66, body extent -0.8,-0.4 0.8,0.4, height 0.72
SOT-323 [mm] "Diodes Inc recommended land pattern.  2016-02-24"
  rrect21% 0.6x0.47 smd: 1(-0.95,0.65) 2(-0.95,-0.65) 3(0.95,0)
  silkscreen extent -1.14,-1.22 0.77,1.22, body extent -1.13,-1.13 1.12,1.12, height 1.13
WE-XHMI_6060 [mm] "SMD, 2-Leads, Body 6.65x6.45mm"
  rrect7% 1.45x5.5 smd: 1(-2,0) 2(2,0)
  body extent -3.22,-3.32 3.22,3.32, height 5.78
WSL0805 [mm] "Vishay"
  rect 1.02x1.27 smd: 1(-0.76,0) 2(0.76,0)
  silkscreen extent -0.6,-0.9 0.6,0.9, body extent -1.14,-0.76 1.14,0.76, height 0.59

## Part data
C1 C35: library part NPXH0701E151MJTM, Voltage=25V
C2 C23: library part CMP-0006310-2, "CAP, CERM, 150 pF, 50 V, +/- 5%, C0G/NP0, AEC-Q200 Grade 1, 0402", Cap_Case=0402, Manufacturer=TDK, Supplier Part Number 1=445-5598-1-ND, TempCo=C0G/NP0, Tolerance_%=5%, Value1=Unknown, Value2=50V, ValueDisplayed=150pF
C3 C5: library part CMP-0860983-1, "CAP, CERM, 0.1 µF, 50 V,+/- 10%, X7R, 0402", Cap_Case=0402, Manufacturer="Passive Plus", TempCo=X7R, Tolerance_%=10%, Value2=50V, ValueDisplayed=0.1µF
C4 C6: library part CMP-0006280-2, "CAP, CERM, 0.047 uF, 50 V, +/- 10%, X5R, 0402", Cap_Case=0402, Manufacturer=TDK, Supplier Part Number 1=445-7382-1-ND, TempCo=X5R, Tolerance_%=10%, Value1="0.06407 ohm", Value2=50V, ValueDisplayed=0.047uF
C27 C28 C33 C36 C42 C59: library part CMP-0083708-1, "CAP, CERM, 10 µF, 35 V,+/- 10%, X5R, 0805", Cap_Case=0805, Manufacturer="Taiyo Yuden", Supplier Part Number 1=587-4893-1-ND, TempCo=X5R, Tolerance_%=10%, Value2=35V, ValueDisplayed=10µF
C29 C38 C39 C40: library part CMP-0006370-1, "CAP, CERM, 0.1 uF, 35 V, +/- 10%, X5R, 0402", Cap_Case=0402, Manufacturer="Taiyo Yuden", Supplier Part Number 1=587-1994-1-ND, TempCo=X5R, Tolerance_%=10%, Value1=Unknown, Value2=35V, ValueDisplayed=0.1uF
C34 C53: library part CMP-0006610-2, "CAP, CERM, 2.2 uF, 25 V, +/- 10%, X5R, 0402", Cap_Case=0402, Manufacturer=MuRata, Supplier Part Number 1=GRM155R61E225KE11D-ND, TempCo=X5R, Tolerance_%=10%, Value1=Unknown, Value2=25V, ValueDisplayed=2.2uF
C44 C46: library part CMP-0006608-2, "CAP, CERM, 1 uF, 25 V, +/- 10%, X5R, 0402", Cap_Case=0402, Manufacturer=MuRata, Supplier Part Number 1=490-10017-1-ND, TempCo=X5R, Tolerance_%=10%, Value1=Unknown, Value2=25V, ValueDisplayed=1uF
C47 C55 C60 C62: library part CMP-0006682-1, "CAP, CERM, 220 pF, 50 V, +/- 10%, X7R, 0402", Cap_Case=0402, Manufacturer=MuRata, Supplier Part Number 1=490-1298-1-ND, TempCo=X7R, Tolerance_%=10%, Value1=Unknown, Value2=50V, ValueDisplayed=220pF
C57 C58: library part CMP-0006319-1, "CAP, CERM, 3300 pF, 50 V, +/- 10%, X7R, AEC-Q200 Grade 1, 0402", Cap_Case=0402, Manufacturer=TDK, Supplier Part Number 1=445-6891-1-ND, TempCo=X7R, Tolerance_%=10%, Value1="0.785178 ohm", Value2=50V, ValueDisplayed=3300pF
D6 D11: library part CMP-0074704-3, "Diode, Schottky, 40 V, 0.2 A, SOD-523", Manufacturer=Rohm, Supplier Part Number 1=RB521SM-40T2RDKR-ND, Value1=0.2A, Value2=0.54V
D8 D9 D10 D12: library part CMP-0092592-1, "18V Clamp 22A (8/20µs) Ipp Tvs Diode Surface Mount SOD-323", Breakdown Voltage=5.5V, Clamping Voltage=18V, Digikey Part Number=283-STS321050B331CT-ND, Manufacturer=Eaton, Mouser Part Number=504-STS321050B331, Operating Temperature Range="-55°C to +125°C", ValueDisplayed=33pF
J3 J5: library part CMP-0120965-1, "USB Connectors USB-C Rec 3u Vert 16P SMT 2.3mm TH stakes H7.46mm T+R+Cap", Current_A=6.25A, Digikey Part Number=2073-USB4145-03-0230-CCT-ND, Manufacturer=GCT, Mouser Part Number=640-USB4145-3-0230-C, Operating Temperature Range="-25°C to +85°C", Voltage_V=48V
L2 L3: library part CMP-0085368-1, "Inductor, Shielded, Hyperflux, 5.6 µH, 6.9 A, 0.0165 ohm, SMD", Manufacturer="Wurth Elektronik", Value1="0.0165 ohm", Value2=6.9A, ValueDisplayed=5.6µH
Q2 Q4: library part CMP-0000774-1, "MOSFET, N-CH, 60 V, 0.31 A, SOT-323", Alternate Manufacturer=None, Manufacturer="Fairchild Semiconductor", Supplier Part Number 1=2N7002KWCT-ND, Value1=1
Q3 Q5: library part MOSFET_N_D56789G4S123, "MOSFET, N-CH, 30 V, 60 A, DQG0008A (VSON-CLIP-8)", Alternate Manufacturer=None, Manufacturer="Texas Instruments", Supplier Part Number 1=296-39994-1-ND, Value1=0.003, Value2="23 nC"
R1 R3 R18 R20 R40 R44 R51 R55: library part CMP-0026866-2, "RES, 1.0, 5%, 0.063 W, 0402", Manufacturer=Vishay-Dale, Power_W=63mW, Supplier Part Number 1=541-1.0JCT-ND, TempCo="200 ppm/C", Tolerance_%=5%, Value2=0.063W, Value_Code=1R00, ValueDisplayed=1.0
R2 R4: library part CMP-0026284-1, "RES, 30.1 k, 1%, 0.063 W, 0402", Manufacturer=Vishay-Dale, Power_W=63mW, Supplier Part Number 1=541-30.1KLCT-ND, TempCo="100 ppm/C", Tolerance_%=1%, Value2=0.063W, Value_Code=30k1, ValueDisplayed=30.1k
R23 R24: library part CMP-0021978-2, "RES, 0.005, 1%, 0.25 W, 0805", Manufacturer=Vishay-Dale, Power_W=250mW, TempCo="110 ppm/C", Tolerance_%=1%, Value2=0.25W, Value_Code=5L000, ValueDisplayed=0.005
R26 R27: library part CMP-0026768-1, "RES, 100 k, 0.5%, 0.063 W, 0402", Manufacturer=Vishay-Dale, Power_W=63mW, Supplier Part Number 1=541-100KAVCT-ND, TempCo="50 ppm/C", Tolerance_%=0.5%, Value2=0.063W, Value_Code=100k
R28 R29: library part CMP-0026467-2, "RES, 5.62 k, 1%, 0.063 W, AEC-Q200 Grade 0, 0402", Manufacturer=Vishay-Dale, Power_W=63mW, Supplier Part Number 1=541-5.62KLCT-ND, TempCo="100 ppm/C", Tolerance_%=1%, Value2=0.063W, Value_Code=5k62, ValueDisplayed=5.62k
R30 R33: library part CMP-0026016-3, "RES, 14.3 k, 1%, 0.063 W, AEC-Q200 Grade 0, 0402", Manufacturer=Vishay-Dale, Power_W=63mW, Supplier Part Number 1=541-14.3KLCT-ND, TempCo="100 ppm/C", Tolerance_%=1%, Value2=0.063W, Value_Code=14k3, ValueDisplayed=14.3k
R45 R52 R56 R57 R59 R62: library part CMP-0026716-1, "RES, 1.00 k, 1%, 0.063 W, 0402", Manufacturer=Rohm, Power_W=63mW, Supplier Part Number 1=RHM1.00KLCT-ND, TempCo="100 ppm/C", Tolerance_%=1%, Value2=0.063W, Value_Code=1k00, ValueDisplayed=1.00k
R46 R63: library part CMP-0026827-3, "RES, 1.00 M, 1%, 0.063 W, AEC-Q200 Grade 0, 0402", Manufacturer="Stackpole Electronics Inc", Power_W=63mW, Supplier Part Number 1=RMCF0402FT1M00CT-ND, TempCo="200 ppm/C", Tolerance_%=1%, Value2=0.063W, Value_Code=1.0Meg, ValueDisplayed=1.00M
R47 R48 R64 R66: library part CMP-0026463-2, "RES, 47, 5%, 0.063 W, 0402", Manufacturer=Vishay-Dale, Power_W=63mW, Supplier Part Number 1=541-47JCT-ND, TempCo="200 ppm/C", Tolerance_%=5%, Value2=0.063W, Value_Code=47
R49: library part CMP-0095068-1, "Chip NTC Thermistors (Sensor), Resistance (at 25°C)=10kΩ, Resistance Tolerance (at 25°C)=±1%", B Tolerance=1%, Manufacturer=TDK, Operating Temperature Range="to +125°C"
R54 R58: library part CMP-0026158-1, "RES, 200 k, 1%, 0.063 W, 0402", Manufacturer=Vishay-Dale, Power_W=63mW, Supplier Part Number 1=541-200KLCT-ND, TempCo="100 ppm/C", Tolerance_%=1%, Value2=0.063W, Value_Code=200k
U1 U2: library part CMP-0097667-3, "4.5-V to 28-V Input, 8-A Synchronous Buck Converter", Manufacturer="Texas Instruments", Max Supply Voltage=28V, Min Supply Voltage=4.5V, Nominal Supply Current=50uA, Operating Temperature Range="-40°C to +150°C", Output Voltage=0.6-13V, Switching Frequency=500/800/1200kHz
U6: library part CMP-0034271-1, "150-mA 30-V low-dropout (LDO) linear regulator with 3.2-μA supply current 5-SOT-23 -40 to 125", Digikey Part Number=296-TLV709A33DBVRCT-ND, Dropout Voltage=1000mV, Manufacturer="Texas Instruments", Max Supply Voltage=30V, Min Supply Voltage=4.3V, Mouser Part Number=595-TLV709A33DBVR, Nominal Supply Current=3.2uA, Operating Temperature Range="-40°C to +125°C", Output Voltage=3.3V
U7: library part U?, "IP2738 dual port USB PD controller"

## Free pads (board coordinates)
  rect 4.5x1.6 smd: N(0.42,13.318)
  rect 4.5x1.6 smd far side: N(0.442,16.124)
  rect 3x1.6 smd: N(1.209,16.131)

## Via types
v1: diameter 0.5, hole 0.25, Top Layer to Bottom Layer, 93 vias
v2: diameter 0.3, hole 0.2, Top Layer to Bottom Layer, tented both sides, 69 vias
v3: diameter 0.5, hole 0.3, Top Layer to Bottom Layer, tented both sides, 27 vias
v4: diameter 0.4, hole 0.2, Top Layer to Bottom Layer, tented both sides, 16 vias
v5: diameter 0.5, hole 0.25, Top Layer to Bottom Layer, tented both sides, 7 vias

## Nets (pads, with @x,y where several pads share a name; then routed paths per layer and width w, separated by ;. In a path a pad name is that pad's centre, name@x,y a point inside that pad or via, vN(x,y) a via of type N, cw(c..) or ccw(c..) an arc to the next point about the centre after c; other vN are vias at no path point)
CC1_A: D8.2 J3.A5 R47.2 | length 3.9
  Top Layer w0.2: v2(-19.044,14.236) -19.016,14.236 -18.754,13.974 -17.078,13.974 D8.2@-17.025,14.026
  Bottom Layer w0.2: v2@-19.044,14.216 v2(-19.044,14.236) -19.033,14.247 -19.033,15.176 J3.A5@-19.03,15.178 ; v2(-16.792,14.239) -16.498,13.945 R47.2@-16.12,13.945
CC1_B: D10.2 J5.A5 R64.2 | length 2.5
  Top Layer w0.254: v2(-16.428,12.441) -16.407,12.461 D10.2@-16.407,12.617
  Bottom Layer w0.254: J5.A5@-17.568,11.434 -17.557,11.445 -17.557,12.151 -17.283,12.425 -16.475,12.425 -16.469,12.432 -16.449,12.432 v2@-16.443,12.425 ; v2@-16.415,12.441 -16.37,12.485 -16.253,12.485 -16.189,12.549 R64.2@-16.189,12.663
CC2_A: D9.2 J3.B5 R48.2 | length 10
  Top Layer w0.2: D9.2@-17.759,16.595 -17.459,16.295 -17.459,16.252 -16.78,15.572 -16.78,15.567 -16.457,15.245 -16.452,15.245 -16.333,15.126 -16.31,15.126 -16.26,15.076 v2(-16.232,15.076) ; D9.2@-17.69,16.713 -17.508,16.895 -17.508,17.416 v2(-17.504,17.419)
  Signal Layer 1 w0.2: v2(-17.504,17.419) v2@-17.488,17.403 ; v2(-16.232,15.076) -16.232,15.049 -16.102,14.918 -16.102,14.635 -15.827,14.36 -13.066,14.36 -12.851,14.575 v2(-12.851,16.822)
  Bottom Layer w0.2: J3.B5@-17.522,18.179 -17.513,18.171 -17.513,17.428 v2(-17.504,17.419)
CC2_B: D12.2 J5.B5 R66.2 | length 11.3
  Top Layer w0.254: v2(-19.074,7.837) -19.065,7.846 -19.065,8.057 -18.092,9.029 -17.834,9.029 -17.504,9.359 -17.488,9.375 -17.488,9.477 v2(-17.504,9.493)
  Signal Layer 1 w0.254: v2(-19.074,7.837) v2@-19.065,7.846 ; v2@-17.513,9.484 v2(-17.504,9.493) -16.167,9.493 -15.465,8.791 -15.465,7.878 -15.132,7.545 -13.524,7.545 -13.025,8.043 v2(-13.025,10.146)
  Bottom Layer w0.254: v2(-19.074,7.837) -19.071,7.84 -19.071,8.462 J5.B5@-19.068,8.464
DM_A: J3.A7 J3.B7 U7.21 | length 10.9
  Signal Layer 1 w0.2: v2(-17.929,14.424) -17.91,14.404 -17.91,14.317 -17.381,13.789 -14.947,13.789 -14.777,13.959 v2(-12.148,13.959)
  Bottom Layer w0.2: J3.B7@-18.522,18.179 -18.513,18.17 -18.513,16.699 -18.063,16.249 -18.063,15.25 -17.972,15.159 -17.972,14.494 -17.929,14.451 v2(-17.929,14.424) ; v2@-12.147,13.958 U7.21@-11.377,13.957
DM_B: J5.A7 J5.B7 U7.17 | length 14.3
  Signal Layer 1 w0.2: v2(-18.581,12.321) -18.554,12.321 -18.425,12.191 -17.365,12.191 -16.97,11.797 -16.97,10.625 -16.969,10.623 -16.969,10.394 v2(-16.949,10.375) -16.947,10.375 -16.782,10.21 -15.925,10.21 -15.808,10.327 -15.808,11.739 -15.151,12.395 -13.321,12.395 v2(-12.841,11.916)
  Bottom Layer w0.254: v2(-18.581,12.321) -18.575,12.314 -18.575,11.459 J5.A7@-18.572,11.456 ; J5.B7@-18.068,8.464 -18.068,9.325 -17.983,9.411 -17.983,9.75 -17.366,10.366 v2@-16.958,10.366 ; v2(-12.841,11.916) -11.881,11.916 -11.839,11.957 U7.17@-11.381,11.957
DP_A: J3.A6 J3.B6 U7.20 | length 12.4
  Signal Layer 1 w0.2: v2(-18.042,17.44) -18.529,16.953 v2(-18.529,14.447) -18.529,14.42 -18.51,14.401 -18.51,14.268 -17.631,13.389 -14.781,13.389 -14.704,13.466 -12.194,13.466 v2(-12.181,13.453)
  Bottom Layer w0.2: v2(-18.529,14.447) -18.525,14.451 -18.525,15.206 J3.A6@-18.522,15.209 ; v2(-18.042,17.44) -18.032,17.45 -18.032,18.169 J3.B6@-18.022,18.179 ; v2(-12.181,13.453) -12.179,13.455 -11.379,13.455 U7.20@-11.377,13.457
DP_B: J5.A6 J5.B6 U7.16 | length 13.3
  Signal Layer 1 w0.2: v2(-18.062,12.675) -18.041,12.675 -17.734,12.982 -13.259,12.982 -11.839,11.562 v2(-11.839,11.034)
  Bottom Layer w0.254: J5.B6@-18.568,8.464 -18.568,9.467 -18.437,9.599 -18.437,10.11 -18.072,10.475 J5.A6@-18.072,11.431 ; J5.A6@-18.067,11.436 -18.067,12.67 v2(-18.062,12.675) ; v2(-11.839,11.034) -10.498,11.034 U7.16@-10.477,11.057 U7.16@-10.477,11.057
  other v2: -18.568,7.879
EN_AA: Q2.1 R20.1 | length 12.4
  Signal Layer 1 w0.2: v2(-6.145,8.906) -6.145,9.508 -3.865,11.788 -3.865,13.532 -3.953,13.621 -3.953,13.993 -3.893,14.053 -3.893,16.763 -3.875,16.781 -3.875,19.52 -3.675,19.72 -3.675,20.051 v2(-3.656,20.07)
  Bottom Layer w0.2: R20.1@-6.299,8.912 -6.296,8.909 -6.148,8.909 v2(-6.145,8.906)
EN_BB: Q4.1 R18.1 | length 5
  Bottom Layer w0.2: Q4.1@-11.38,7.221 -11.315,7.221 -9.984,8.553 -7.539,8.553 -7.379,8.713 -7.379,8.827 -7.288,8.918 R18.1@-7.174,8.918
FB_A: R27.1 R29.2 R56.1 | length 1.3
  Bottom Layer w0.2: R56.1@-6.42,20.542 -6.429,20.551 R29.2@-6.429,21.36 -6.425,21.364 R27.1@-5.978,21.364 R27.1@-5.99,21.352
FB_ACDC: pad.N@1.209,16.131 R55.1 | length 7.2
  Top Layer w0.2: v2(0.575,14.664) 0.581,14.67 0.97,14.67 v2(0.975,14.676) 0.975,15.898 pad.N@1.209,16.131
  Signal Layer 1 w0.2: v2(-3.504,13.807) -1.922,13.807 -1.063,14.667 0.572,14.667 v2(0.575,14.664) 0.581,14.67 0.97,14.67 v2(0.975,14.676)
  Bottom Layer w0.2: v2(0.575,14.664) 0.581,14.67 0.97,14.67 v2(0.975,14.676)
FB_B: R26.1 R28.2 R59.1 | length 13.8
  Signal Layer 1 w0.2: v2(-5.084,8.901) -4.77,8.901 -1.77,5.901 -1.77,2.307 -3.086,0.991 v2(-4.979,0.991)
  Bottom Layer w0.2: R28.2@-4.943,0.994 -4.941,0.993 -4.917,0.993 -4.827,1.083 R26.1@-4.268,1.083 ; R26.1@-4.268,1.083 R26.1@-4.178,0.993 ; R26.1@-4.268,1.083 R26.1@-4.178,0.993 ; R26.1@-4.268,1.083 R26.1@-4.178,0.993 ; R26.1@-4.268,1.083 R26.1@-4.178,0.993 ; R26.1@-4.178,0.878 R26.1@-4.178,0.993 ; R26.1@-4.178,0.878 R26.1@-4.178,0.993 ; R26.1@-4.178,0.878 R26.1@-4.178,0.993 ; R26.1@-4.178,0.878 R26.1@-4.178,0.993
  Bottom Layer w0.254: R59.1@-5.295,8.912 -5.231,8.976 R59.1@-5.117,8.976
NetC2_2: C2.2 R29.1 R30.2 U1.2 | length 3.8
  Bottom Layer w0.2: U1.2@-8.091,22.612 -8.091,21.891 -8.015,21.891 -8.006,21.882 -8.006,21.633 R30.2@-7.961,21.588 ; R30.2@-7.917,21.544 -7.897,21.564 -7.535,21.564 R29.1@-7.535,21.557 ; C2.2@-6.003,22.203 -6.337,22.203 -6.46,22.08 -6.689,22.08 -7.205,21.564 -7.354,21.564 -7.445,21.474 R29.1@-7.445,21.36 ; R29.1@-7.535,21.557 R29.1@-7.445,21.466 ; R29.1@-7.535,21.557 R29.1@-7.445,21.466 ; R29.1@-7.445,21.36 R29.1@-7.445,21.466 ; R29.1@-7.445,21.36 R29.1@-7.445,21.466
NetC3_1: C3.1 R1.2 | length 0.7
  Bottom Layer w0.2: R1.2@-10.624,26.28 -10.624,25.631 C3.1@-10.573,25.58
NetC3_2: C3.2 L2.1 U1.6
NetC4_1: C4.1 U1.5 | length 1.8
  Bottom Layer w0.254: C4.1@-10.052,21.486 -9.938,21.486 -9.764,21.66 -9.764,23.08 -9.763,23.082 U1.5@-9.741,23.082
NetC5_1: C5.1 R3.2 | length 0.6
  Bottom Layer w0.2: R3.2@-10.887,6.256 -10.887,5.665 C5.1@-10.876,5.654
NetC5_2: C5.2 L3.1 U2.6 | length 2
  Bottom Layer w0.2: L3.1@-15.182,1.207 L3.1@-13.157,1.207
NetC6_1: C6.1 U2.5 | length 1.5
  Bottom Layer w0.2: U2.5@-9.763,3.317 -9.763,1.904 C6.1@-9.736,1.877
NetC23_2: C23.2 R28.1 R33.2 U2.2 | length 5.8
  Bottom Layer w0.2: U2.2@-8.113,2.847 U2.2@-8.113,2.847 -8.112,2.303 -7.764,1.954 -7.288,1.954 R33.2@-6.437,1.102 ; C23.2@-4.317,1.757 -4.317,1.796 -4.408,1.887 -5.659,1.887 -6.023,1.522 -6.023,1.059 R28.1@-5.958,0.994 -6.346,0.994 -6.349,0.997 -6.349,1.059 R33.2@-6.42,0.988 ; R33.2@-6.42,0.988 R33.2@-6.437,0.988 R33.2@-6.42,0.988
NetC44_1: C44.1 R40.1 U7.32 | length 2.9
  Bottom Layer w0.2: U7.32@-6.977,16.357 -6.977,17.555 -6.749,17.782 -6.749,18.321 C44.1@-6.797,18.369 ; C44.1@-6.755,18.369 -6.74,18.353 -6.004,18.353 R40.1@-5.989,18.338
NetC46_1: C46.1 R44.1 U7.31 | length 3.7
  Bottom Layer w0.2: R44.1@-8.438,19.4 -8.324,19.4 -8.233,19.31 -8.233,19.105 -8.042,18.913 -7.749,18.913 -7.632,18.796 -7.632,18.415 C46.1@-7.615,18.398 -7.567,18.398 -7.477,18.307 U7.31@-7.477,16.357
NetC53_2: C53.2 R51.2 U7.1 | length 3.7
  Top Layer w0.2: v2(-4.849,17.254) -4.822,17.254 -4.693,17.383 -4.417,17.383 -4.327,17.473 R51.2@-4.212,17.473
  Bottom Layer w0.2: U7.1@-6.077,15.457 -5.767,15.457 -5.72,15.503 -5.72,16.195 -5.518,16.397 -4.885,16.397 C53.2@-4.795,16.397 -4.83,16.433 -4.83,17.235 v2(-4.849,17.254)
NetC57_1: C57.1 R58.1 | length 0.9
  Bottom Layer w0.2: C57.1@-4.231,9.483 -4.229,9.486 -3.384,9.486 R58.1@-3.381,9.488
NetC57_2: C57.2 R59.2 U7.8 | length 3.5
  Bottom Layer w0.2: U7.8@-6.077,11.957 -6.05,11.931 -6.05,10.811 -5.231,9.992 R59.2@-5.117,9.992 -5.027,10.082 -4.762,10.082 -4.346,10.499 C57.2@-4.231,10.499
NetC58_1: C58.1 R54.1 | length 2.1
  Bottom Layer w0.2: R54.1@-3.462,14.683 -3.462,14.569 -3.371,14.478 -3.232,14.478 -3.021,14.266 -3.021,13.408 -3.123,13.305 -3.123,13.304 -3.304,13.123 C58.1@-3.304,13.009
NetC58_2: C58.2 R56.2 U7.5 | length 13.4
  Signal Layer 1 w0.2: v2(-7.447,20.481) -7.447,20.508 -7.145,20.81 -7.145,20.811 -6.901,21.055 -4.47,21.055 -4.306,20.891 -4.306,14.207 -4.353,14.159 -4.353,13.455 -4.306,13.407 -4.306,13.144 -4.364,13.086 v2(-4.364,13.059)
  Bottom Layer w0.2: U7.5@-6.077,13.457 -5.14,13.457 -4.915,13.233 -4.911,13.233 -4.892,13.213 -4.411,13.213 -4.37,13.173 -4.37,13.059 C58.2@-4.32,13.009 -4.32,13.014 v2(-4.364,13.059)
NetQ2_3: Q2.3 U1.1 | length 5.8
  Signal Layer 1 w0.2: v2(-7.423,22.603) -8.068,21.958 -8.068,20.973 -8.067,20.971 -8.067,20.599 -8.068,20.597 -8.068,20.134 -7.573,19.639 v2(-5.62,19.639)
  Bottom Layer w0.2: U1.1@-7.592,22.612 -7.587,22.608 -7.428,22.608 v2(-7.423,22.603) ; v2(-5.62,19.639) -5.601,19.62 -5.601,19.541 Q2.3@-5.503,19.444
NetQ4_3: Q4.3 U2.1 | length 7.5
  Signal Layer 1 w0.2: v2(-9.238,6.207) -8.056,6.207 -7.534,5.685 -7.534,2.419 v2(-7.519,2.404)
  Bottom Layer w0.2: Q4.3@-9.48,7.871 -9.48,6.982 -9.255,6.757 -9.255,6.223 v2(-9.238,6.207) ; U2.1@-7.613,2.847 -7.613,2.843 -7.612,2.842 -7.612,2.525 -7.519,2.431 v2(-7.519,2.404)
NetR1_1: R1.1 U1.7 | length 1.5
  Bottom Layer w0.2: U1.7@-9.741,24.882 -9.634,24.882 -9.608,24.907 R1.1@-9.608,26.28
NetR2_2: R2.2 U1.10 | length 4.3
  Signal Layer 1 w0.2: v2(-8.517,20.785) -8.517,22.146 -7.609,23.053 -6.48,23.053 v2(-6.465,23.068)
  Bottom Layer w0.2: U1.10@-6.941,23.082 -6.934,23.075 -6.472,23.075 v2(-6.465,23.068)
NetR3_1: R3.1 U2.7 | length 1.2
  Bottom Layer w0.2: R3.1@-9.872,6.256 -9.83,6.214 -9.83,5.142 -9.804,5.117 U2.7@-9.763,5.117
NetR4_2: R4.2 U2.10 | length 2.9
  Signal Layer 1 w0.2: v2(-8.106,0.93) -8.086,0.949 -7.981,0.949 -7.462,1.468 -6.943,1.987 v2(-6.943,3.007)
  Bottom Layer w0.2: U2.10@-6.963,3.317 -6.953,3.306 -6.953,3.017 v2(-6.943,3.007)
NetR18_2: R18.2 U7.10 | length 1.3
  Bottom Layer w0.2: U7.10@-7.477,11.057 -7.477,10.122 -7.288,9.934 R18.2@-7.174,9.934
NetR20_2: R20.2 U7.9 | length 1.5
  Bottom Layer w0.2: U7.9@-6.977,11.057 -6.977,10.634 -6.931,10.588 -6.885,10.588 -6.503,10.207 -6.503,10.019 -6.413,9.928 R20.2@-6.299,9.928
NetR49_1: R49.1 U7.24 | length 2
  Bottom Layer w0.2: R49.1@-11.706,17.351 -11.456,17.102 -11.456,15.503 -11.41,15.457 U7.24@-11.377,15.457
NetR52_2: R52.2 U7.2 | length 1.7
  Bottom Layer w0.2: U7.2@-6.077,14.957 -5.289,14.957 -4.987,15.259 -4.822,15.259 -4.676,15.405 R52.2@-4.676,15.519
NetR54_2: R54.2 U7.3 | length 1.7
  Bottom Layer w0.2: U7.3@-6.077,14.457 -6.058,14.476 -5.537,14.476 -5.507,14.506 -4.568,14.506 -4.478,14.597 R54.2@-4.478,14.683
NetR55_2: R55.2 U7.4 | length 1.6
  Bottom Layer w0.2: U7.4@-6.077,13.957 -4.618,13.957 -4.527,13.867 R55.2@-4.527,13.837
NetR57_2: R57.2 U7.6 | length 2.3
  Bottom Layer w0.2: U7.6@-6.077,12.957 -5.205,12.957 -4.652,12.404 -4.533,12.404 -4.341,12.212 R57.2@-4.341,12.098 -4.341,12.191 v2(-4.315,12.217)
NetR58_2: R58.2 U7.7 | length 4.2
  Top Layer w0.2: v2(-3.379,10.503) v2(-3.371,10.503)
  Signal Layer 2 w0.2: v2(-5.189,12.304) -5.209,12.285 -5.209,12.214 -5.222,12.2 -5.222,11.245 -4.48,10.503 v2(-3.379,10.503)
  Bottom Layer w0.2: U7.7@-6.077,12.457 -6.058,12.438 -5.351,12.438 -5.217,12.304 v2(-5.189,12.304)
RTN_A: C42.2 D6.2 D8.1 D9.1 J3.1 J3.2 J3.3 J3.4 J3.A1 J3.A12 J3.B1 J3.B12 R23.2 U7.14 | length 30.4
  Top Layer w0.2: R23.2@-22.623,20.806 -22.575,20.758 -21.609,20.758 -21.568,20.717 v3(-21.541,20.717) ; D9.1@-15.559,16.595 J3.2@-14.694,15.73 ; D8.1@-14.825,14.026 -14.708,14.143 -14.708,14.834 -14.278,15.264 J3.2@-14.272,15.264
  Signal Layer 2 w0.2: v3(-21.541,20.717) -21.46,20.717 -21.32,20.578 -21.303,20.578 -20.418,19.693 -8.675,19.693 -7.05,18.067 -7.05,10.96 -7.855,10.155 -9.307,10.155 -9.439,10.022 v4(-9.493,10.022)
  Bottom Layer w0.2: v4(-9.493,10.022) -9.485,10.031 -9.485,11.049 U7.14@-9.477,11.057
